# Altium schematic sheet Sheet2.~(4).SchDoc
size A4
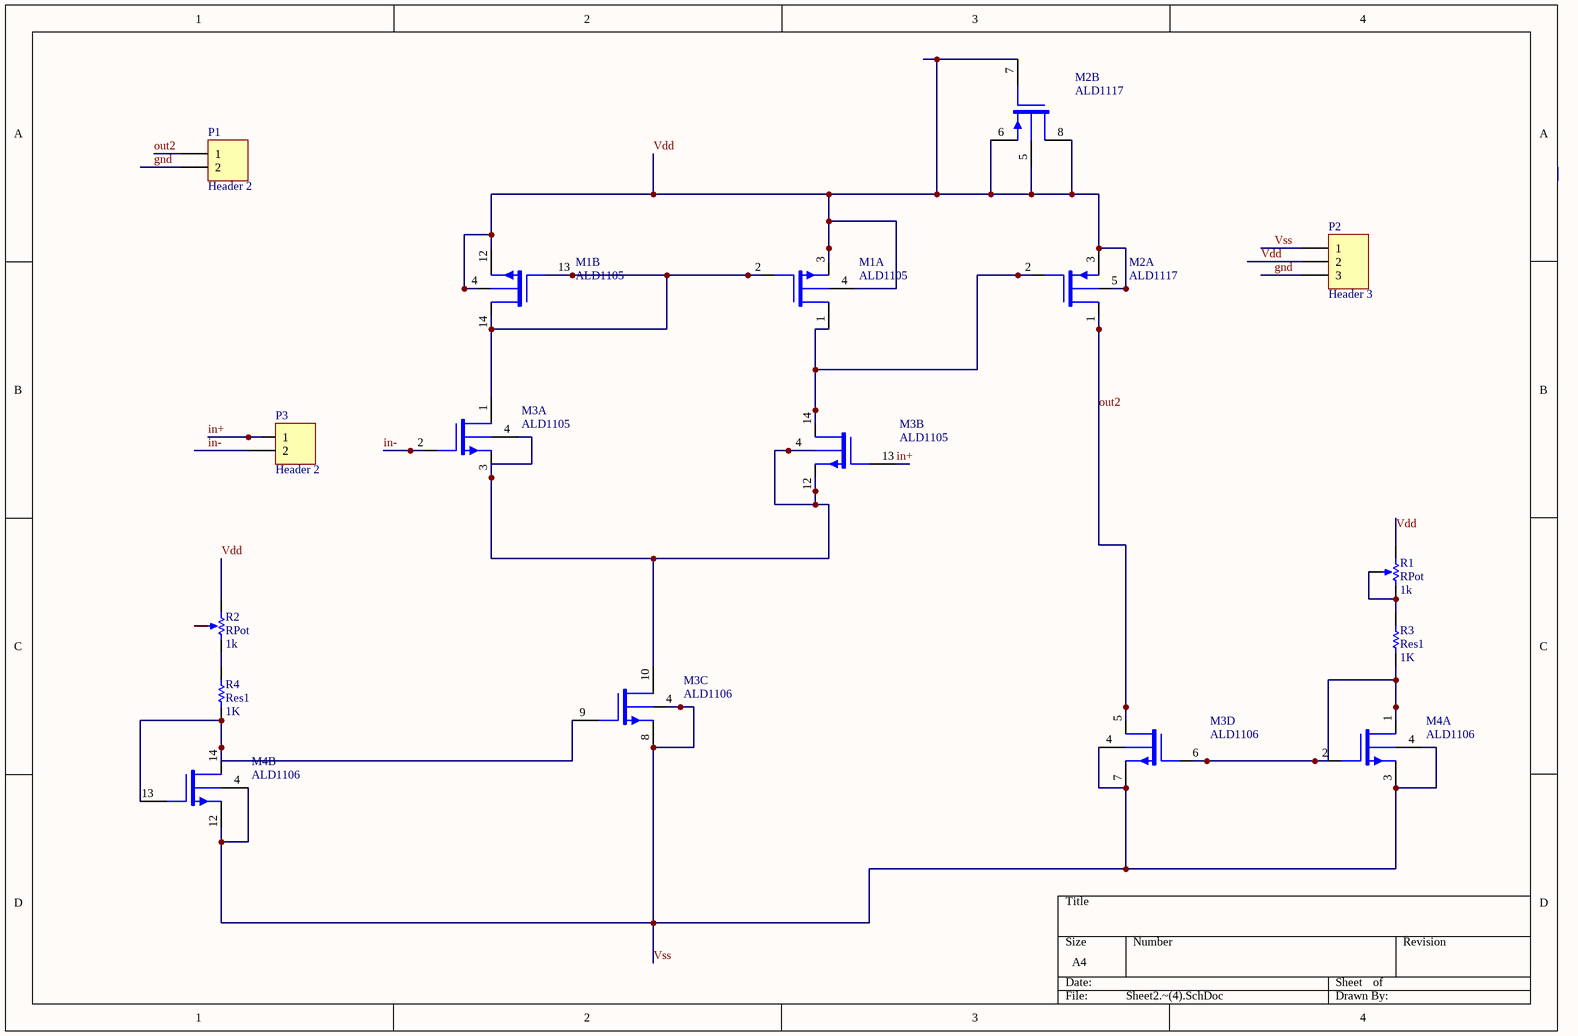
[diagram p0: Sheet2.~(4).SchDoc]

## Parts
(Parts that share a designator on the sheet are numbered #1, #2 ... from top to bottom, then left to right.)
M1  ALD1105  [DIP-14]  (parts A,B of 4)
M2  ALD1117  [DIP-8]  (parts A,B of 2)
M3#1  ALD1105  [DIP-14]  (parts A,B of 4)
M3#2  ALD1106  [DIP-14]  (parts C,D of 4)
M4  ALD1106  [DIP-14]  (parts A,B of 4)
P1  Header 2  [HDR1X2]
P2  Header 3  [HDR1X3]
P3  Header 2  [HDR1X2]
R1  RPot  value 1k  [VR5]
R2  RPot  value 1k  [VR5]
R3  Res1  value 1K  [AXIAL-0.3]
R4  Res1  value 1K  [AXIAL-0.3]

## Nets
gnd: P1.2 P2.3
in+: M3#1.13(GN2) P3.1
in-: M3#1.2(GN1) P3.2
out2: M2.1(DP1) M3#2.5(DN4) P1.1
Vdd: M1.3(SN1) M1.4(V-) M1.12(SN2) M2.3(SP1) M2.5(V+) M2.6(SP2) M2.7(GP2) M2.8(DP2) P2.2 R1.1(TOP) R2.1(TOP)
Vss: M3#2.4(V-) M3#2.7(SN4) M3#2.8(SN3) M4.3(SN1) M4.4(V-) M4.12(SN2) P2.1
NetM1_1: M1.1(DN1) M2.2(GP1) M3#1.14(DN2)
NetM1_2: M1.2(GN1) M1.13(GN2) M1.14(DN2) M3#1.1(DN1)
NetM3#1_3: M3#1.3(SN1) M3#1.4(V-) M3#1.12(SN2) M3#2.10(DN3)
NetM3#2_6: M3#2.6(GN4) M4.1(DN1) M4.2(GN1) R3.2
NetM3#2_9: M3#2.9(GN3) M4.13(GN2) M4.14(DN2) R4.2
NetR1_2: R1.2(TAP) R1.3(BOT) R3.1
NetR2_3: R2.3(BOT) R4.1

Not connected (* = marked no-connect by the designer): R2 2(TAP)

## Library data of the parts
M1 M3#1 = ALD1105: Dual P-channel and dual N-channel matched MOSFET array
M2 = ALD1117: Dual P-channel matched MOSFET array
M3#2 M4 = ALD1106: Quad N-channel matched MOSFET array
P1 P3 = Header 2: Header, 2-Pin
P2 = Header 3: Header, 3-Pin
R1 R2 = RPot: Potentiometer; Sim Note: Enter the Resistance value and the set point into parameter fields.; Set Position: 0.5
R3 R4 = Res1: Resistor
